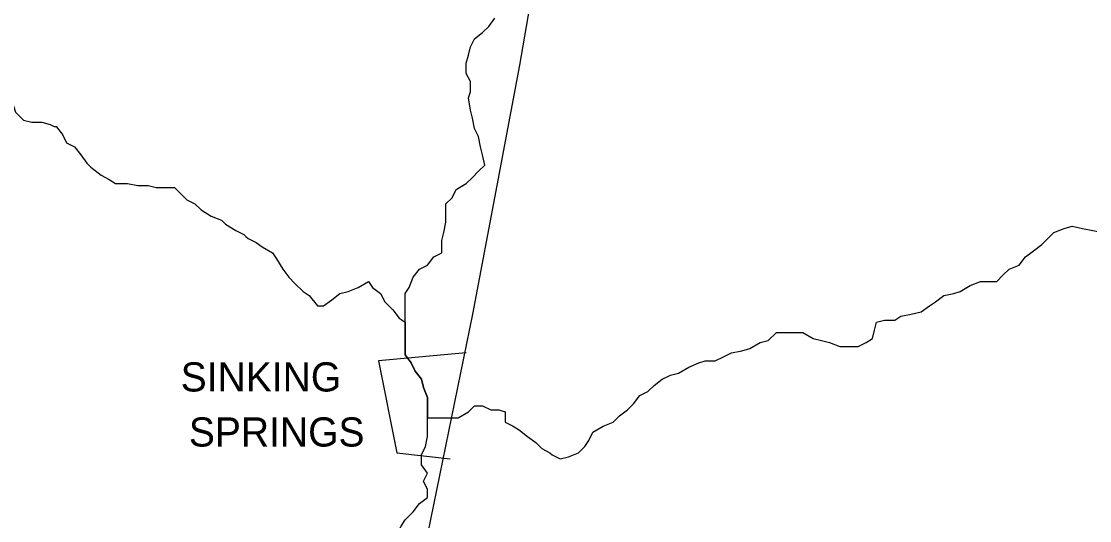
# Model space of a CAD drawing. Extents: x 0 to 34, y 0 to 22.
# Drawn here: x 4.42 to 5.134, y 17.942 to 18.276 of the extents above; entities that cross this region are included whole.
import ezdxf

# ---------------------------------------------------------------- set-up
doc = ezdxf.new("R2010")
doc.units = 0
doc.layers.add('Default', color=7, linetype='Continuous')

msp = doc.modelspace()

# ---------------------------------------------------------------- linework, layer by layer
at = {"layer": 'Default'}
for points in [[(4.8119, 18.57523), (4.78736, 18.44297), (4.76691, 18.32572), (4.75327, 18.24664), (4.73828, 18.1662), (4.72191, 18.0803), (4.69192, 17.93305)], [(4.67692, 18.07485), (4.67692, 18.0803), (4.67692, 18.08576), (4.67692, 18.09394), (4.67965, 18.09803), (4.68238, 18.10485), (4.68647, 18.1103), (4.69192, 18.11303), (4.69601, 18.11848), (4.70146, 18.12121), (4.70146, 18.12939), (4.70283, 18.13484), (4.70419, 18.14166), (4.70419, 18.14711), (4.70419, 18.15393), (4.70828, 18.15802), (4.71101, 18.16347), (4.71782, 18.16756), (4.72191, 18.17165), (4.726, 18.17574), (4.7301, 18.17983), (4.72873, 18.18665), (4.72737, 18.1921), (4.726, 18.19892), (4.72328, 18.20438), (4.72191, 18.21119), (4.72055, 18.21665), (4.71919, 18.22483), (4.72055, 18.22892), (4.72055, 18.23573), (4.71782, 18.24119), (4.71782, 18.248), (4.71919, 18.25346), (4.72055, 18.25891), (4.72328, 18.26437), (4.72873, 18.26846), (4.73282, 18.27255), (4.73691, 18.278)], [(4.33607, 18.26982), (4.34152, 18.26573), (4.34425, 18.26028), (4.3497, 18.25755), (4.35515, 18.25755), (4.36061, 18.25346), (4.3647, 18.25209), (4.37015, 18.25209), (4.37697, 18.24937), (4.38242, 18.24528), (4.38788, 18.24255), (4.39197, 18.23982), (4.39878, 18.23573), (4.40151, 18.23301), (4.40696, 18.22755), (4.40969, 18.22346), (4.41514, 18.21937), (4.41651, 18.21528), (4.42196, 18.20983), (4.42742, 18.20847), (4.43423, 18.20847), (4.43969, 18.2071), (4.44241, 18.20574), (4.44378, 18.20574)], [(4.44378, 18.20574), (4.44787, 18.20029), (4.45059, 18.19483), (4.45605, 18.1921), (4.46014, 18.18665), (4.46423, 18.1812), (4.46695, 18.17847), (4.47377, 18.17302), (4.47923, 18.17029), (4.48332, 18.16756), (4.4915, 18.16756), (4.49831, 18.1662), (4.50513, 18.1662), (4.51058, 18.16484), (4.51604, 18.16484), (4.52286, 18.16484), (4.52695, 18.16075), (4.53104, 18.15666), (4.53649, 18.15393), (4.54058, 18.14984), (4.5474, 18.14575), (4.55421, 18.14302), (4.55694, 18.14029), (4.56376, 18.1362), (4.56921, 18.13348), (4.57057, 18.13211), (4.57194, 18.13075)], [(5.0655, 18.10212), (5.07231, 18.10212), (5.0764, 18.10621), (5.08049, 18.1103), (5.08731, 18.11303), (5.0914, 18.11848), (5.09686, 18.12257), (5.10231, 18.12666), (5.1064, 18.13075), (5.11049, 18.13484), (5.11731, 18.13757), (5.12276, 18.13893), (5.12958, 18.13757), (5.13639, 18.1362), (5.14321, 18.13484), (5.14867, 18.13211), (5.15412, 18.13075), (5.16094, 18.12939), (5.16775, 18.12939), (5.17457, 18.12666), (5.17866, 18.1253), (5.18548, 18.1253), (5.18548, 18.1253)], [(4.57194, 18.13075), (4.57739, 18.12802), (4.58148, 18.1253), (4.5883, 18.12121), (4.59103, 18.11712), (4.59512, 18.1103), (4.59921, 18.10485), (4.6033, 18.10076), (4.60875, 18.0953), (4.61284, 18.09257), (4.61829, 18.08576), (4.62238, 18.08576), (4.62784, 18.08985), (4.63329, 18.09394), (4.63875, 18.0953), (4.64556, 18.09803), (4.65238, 18.10212), (4.65511, 18.09803), (4.66056, 18.09394), (4.66329, 18.08848), (4.66874, 18.08303), (4.67283, 18.07758), (4.67692, 18.07485), (4.67692, 18.07485)], [(4.93052, 18.06803), (4.93734, 18.06803), (4.94279, 18.06803), (4.94961, 18.06394), (4.95506, 18.06258), (4.96051, 18.06122), (4.96733, 18.05849), (4.97278, 18.05849), (4.9796, 18.05849), (4.98505, 18.06122), (4.98915, 18.06394), (4.99051, 18.0694), (4.99187, 18.07485), (4.99733, 18.07621), (5.00414, 18.07621), (5.00823, 18.07894), (5.01505, 18.0803), (5.02187, 18.08167), (5.02732, 18.08576), (5.03141, 18.08848), (5.03686, 18.09257), (5.04368, 18.09394), (5.04777, 18.0953), (5.05459, 18.09939), (5.06141, 18.10212), (5.0655, 18.10212), (5.0655, 18.10212)], [(4.67692, 18.07485), (4.67692, 18.07212), (4.67692, 18.06531), (4.67692, 18.05985), (4.67692, 18.05304), (4.68101, 18.04758), (4.68374, 18.04213), (4.68783, 18.03667), (4.68919, 18.03122), (4.69192, 18.0244), (4.69192, 18.01895), (4.69192, 18.01077)], [(4.69192, 18.01077), (4.69192, 18.01895), (4.69192, 18.0244), (4.68919, 18.03122), (4.68783, 18.03667), (4.68374, 18.04213), (4.68101, 18.04758), (4.67692, 18.05304), (4.67692, 18.05985), (4.67692, 18.06531), (4.67692, 18.07212), (4.67692, 18.07485)], [(4.77509, 17.98623), (4.78054, 17.9835), (4.786, 17.98486), (4.79281, 17.98759), (4.7969, 17.99168), (4.79963, 17.99577), (4.80236, 18.00123), (4.80917, 18.00532), (4.81599, 18.00804), (4.82008, 18.01213), (4.82553, 18.01622), (4.82962, 18.02031), (4.83372, 18.02577), (4.83917, 18.02849), (4.84326, 18.03258), (4.84871, 18.03667), (4.85417, 18.0394), (4.85962, 18.04076), (4.86644, 18.04486), (4.87325, 18.04758), (4.87734, 18.04895), (4.88416, 18.04895), (4.88962, 18.05167), (4.89507, 18.0544), (4.90189, 18.05576), (4.90734, 18.05713), (4.91416, 18.06122), (4.91961, 18.06258), (4.92506, 18.06803), (4.92915, 18.06803), (4.93052, 18.06803), (4.93052, 18.06803)], [(4.71782, 18.0544), (4.6592, 18.04895), (4.67147, 17.98759), (4.70692, 17.9835)], [(4.70828, 18.01077), (4.71237, 18.01077), (4.71919, 18.01486), (4.72328, 18.01895), (4.72873, 18.01895), (4.73419, 18.01622), (4.73964, 18.01622), (4.74373, 18.01486), (4.74373, 18.00804), (4.74918, 18.00532), (4.75327, 18.00259), (4.75873, 17.9985), (4.76418, 17.99441), (4.76827, 17.99032), (4.77372, 17.98759), (4.77372, 17.98759), (4.77509, 17.98623)], [(4.67147, 17.9276), (4.67147, 17.93305), (4.67419, 17.93851), (4.67692, 17.9426), (4.68238, 17.94805), (4.68647, 17.95351), (4.69192, 17.9576), (4.69192, 17.96305), (4.68919, 17.9685), (4.69192, 17.97396), (4.68783, 17.97941), (4.68783, 17.98623), (4.69056, 17.99168), (4.69192, 17.9985), (4.69192, 18.00668), (4.69192, 18.01077), (4.69192, 18.01077)], [(4.69192, 18.01077), (4.69737, 18.01077), (4.70419, 18.01077), (4.70828, 18.01077)]]:
    msp.add_lwpolyline(points, dxfattribs=at)

# ---------------------------------------------------------------- texts
for s, p in [('SINKING', (4.52695, 18.02849)), ('SPRINGS', (4.5324, 17.99168))]:
    msp.add_text(s, height=0.019502, dxfattribs=at).set_placement(p)

doc.saveas('drawing.dxf')
